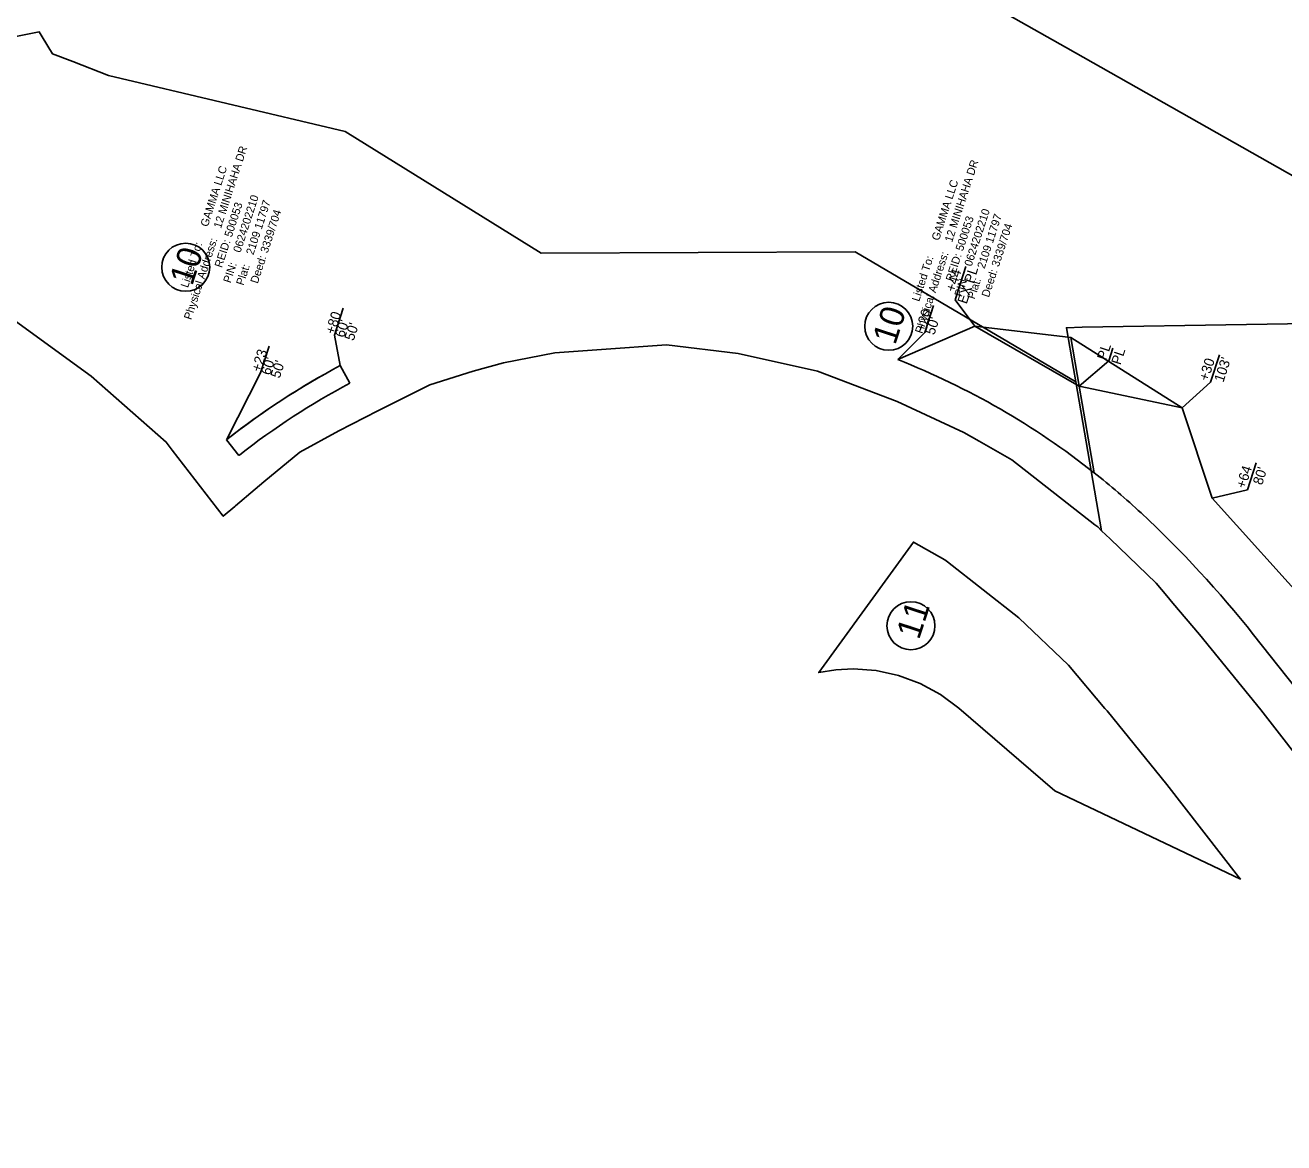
# Model space of a CAD drawing. Extents: x 1019969 to 1024963, y 638146 to 643978.
# Drawn here: x 1022170 to 1022798, y 639826 to 640385 of the extents above; entities that cross this region are included whole.
import ezdxf

# ---------------------------------------------------------------- set-up
doc = ezdxf.new("R2010")
doc.units = 0
for name, color, linetype in [('Old_Level_30', 7, 'Continuous'), ('Pattern 5', 7, 'Continuous'), ('Pattern 6', 7, 'Continuous'), ('Prop Easement Construction', 7, 'Continuous'), ('Prop Easement Construction Station Offsets', 7, 'Continuous'), ('Prop Parcel Number CELL', 7, 'Continuous'), ('Prop Parcel Owner Text', 7, 'Continuous'), ('Prop ROW RW Lines', 7, 'Continuous')]:
    doc.layers.add(name, color=color, linetype=linetype)

msp = doc.modelspace()

# ---------------------------------------------------------------- linework, layer by layer
at = {"layer": 'Old_Level_30'}
for points in [[(1022988.86, 640468.59), (1022949.84, 640356.28), (1022949.73, 640356.05), (1022940.94, 640338.75), (1022939.06, 640335.05), (1022948.94, 640320.64), (1022950.08, 640319.01), (1022927.01, 640297.25), (1022898.56, 640270.43), (1022898.48, 640270.34), (1022888.65, 640261.07), (1022888.56, 640260.99), (1022689.3, 640373.74), (1022582.7, 640434.06)], [(1022148.7, 640375.88), (1022176.6, 640381.39), (1022178.12, 640378.87), (1022183.21, 640370.43), (1022193.31, 640366.53), (1022211.12, 640359.66), (1022329.52, 640331.69), (1022427.3, 640270.8), (1022584.22, 640271.53), (1022694.52, 640206.46), (1022707.44, 640132.03), (1022705.45, 640133.95), (1022704.1, 640135), (1022662.55, 640167.57), (1022646.27, 640176.76), (1022638.51, 640181.14), (1022605.2, 640196.65), (1022565.48, 640211.83), (1022525.74, 640220.72), (1022490.07, 640225.03), (1022457.46, 640222.66), (1022434.16, 640220.91), (1022408.58, 640216.03), (1022393.41, 640211.79), (1022371.78, 640205), (1022345.75, 640191.98), (1022326.36, 640182.01), (1022306.78, 640171.26), (1022288.84, 640156.43), (1022284.55, 640152.82), (1022284.47, 640152.75), (1022274.59, 640144.45), (1022274.24, 640144.15), (1022268.5, 640139.32), (1022243.08, 640172.38), (1022240.04, 640176.35), (1022202.53, 640209.25), (1022162.87, 640238.08)], [(1022814.25, 640007.36), (1022786.96, 640042.51), (1022756.35, 640080.22), (1022743.08, 640095.93), (1022740.03, 640099.54), (1022734.65, 640105.92), (1022711.61, 640128.02), (1022707.44, 640132.03), (1022694.52, 640206.46), (1022693.36, 640213.1), (1022693.35, 640213.19), (1022689.81, 640233.51), (1022697.66, 640233.85), (1022861.98, 640236.45)]]:
    msp.add_lwpolyline(points, dxfattribs=at)
msp.add_lwpolyline([(1022690.83, 640064.81), (1022709.07, 640043.2), (1022710.12, 640041.95), (1022739.96, 640005.2), (1022775.74, 639959.13), (1022776.77, 639957.9), (1022684.01, 640002), (1022636.09, 640043.31), (1022626.86, 640050.19), (1022616.74, 640055.7), (1022605.94, 640059.71), (1022594.69, 640062.15), (1022583.2, 640062.97), (1022574.59, 640062.51), (1022566.08, 640061.14), (1022613.4, 640126.41), (1022629.11, 640117.55), (1022630.4, 640116.54), (1022666.07, 640088.57)], close=True, dxfattribs=at)
at = {"layer": 'Pattern 6'}
for p, q in [((1022644.09, 640234.25), (1022605.57, 640217.59)), ((1022696.24, 640204.35), (1022644.09, 640234.25)), ((1022747.67, 640193.56), (1022692.04, 640228.71)), ((1022692.04, 640228.71), (1022696.24, 640204.35)), ((1022331.77, 640205.78), (1022327.03, 640214.59)), ((1022605.57, 640217.59), (1022605.57, 640217.59)), ((1022703.71, 640161.05), (1022696.24, 640204.35)), ((1022696.24, 640204.35), (1022696.24, 640204.35)), ((1022696.24, 640204.35), (1022696.24, 640204.35)), ((1022696.24, 640204.35), (1022703.71, 640161.05)), ((1022762.71, 640148.33), (1022747.67, 640193.56)), ((1022270.14, 640177.44), (1022276.36, 640169.61)), ((1022965.65, 639922.52), (1022762.71, 640148.33)), ((1022783.3, 640080.08), (1022840.86, 640007.16))]:
    msp.add_line(p, q, dxfattribs=at)
msp.add_lwpolyline([(1022696.24, 640204.35), (1022644.09, 640234.25), (1022692.04, 640228.71)], close=True, dxfattribs=at)
for centre, radius, start, end in [((1022499.92, 639887.66), 369.83, 117.87073, 128.33147), ((1022462.98, 639856.64), 388.09, 51.66236, 68.44413), ((1022499.92, 639887.66), 359.83, 117.8594, 128.33147), ((1022499.92, 639887.66), 369.83, 128.33147, 128.41171), ((1022499.92, 639887.66), 359.83, 128.33147, 128.41171), ((1022462.98, 639856.64), 388.09, 47.09809, 51.66236), ((1022360.48, 639746.34), 538.67, 38.28466, 47.0981)]:
    msp.add_arc(centre, radius, start, end, dxfattribs=at)
at = {"layer": 'Prop Easement Construction'}
for p, q in [((1022605.57, 640217.59), (1022644.09, 640234.25)), ((1022696.24, 640204.35), (1022644.09, 640234.25)), ((1022331.77, 640205.78), (1022327.03, 640214.59)), ((1022747.67, 640193.56), (1022696.24, 640204.35)), ((1022762.71, 640148.33), (1022747.67, 640193.56)), ((1022276.36, 640169.61), (1022270.14, 640177.44)), ((1022967.3, 639920.68), (1022762.71, 640148.33))]:
    msp.add_line(p, q, dxfattribs=at)
msp.add_arc((1022499.92, 639887.66), 369.83, 117.87073, 128.41171, dxfattribs=at)
at = {"layer": 'Prop Easement Construction Station Offsets'}
for p, q in [((1022639.6, 640264.17), (1022634.17, 640247.47)), ((1022623.4, 640244.59), (1022619.02, 640231.12)), ((1022328.47, 640243.27), (1022324.09, 640229.8)), ((1022291.44, 640224.27), (1022287.13, 640211.01)), ((1022713.07, 640223.3), (1022711.04, 640217.04)), ((1022766.24, 640219.93), (1022761.83, 640206.37)), ((1022784.7, 640165.92), (1022780.32, 640152.46))]:
    msp.add_line(p, q, dxfattribs=at)
for points in [[(1022634.17, 640247.47), (1022644.09, 640234.25)], [(1022324.09, 640229.8), (1022327.03, 640214.59)], [(1022619.02, 640231.12), (1022605.57, 640217.59)], [(1022711.04, 640217.04), (1022696.24, 640204.35)], [(1022287.13, 640211.01), (1022270.14, 640177.44)], [(1022761.83, 640206.37), (1022747.67, 640193.56)], [(1022780.32, 640152.46), (1022762.71, 640148.33)]]:
    msp.add_lwpolyline(points, dxfattribs=at)
at = {"layer": 'Prop Parcel Number CELL'}
for p, q in [((1022249.77, 640263.77), (1022249.77, 640263.77)), ((1022601.05, 640234.23), (1022601.05, 640234.23)), ((1022612.16, 640084.58), (1022612.16, 640084.58))]:
    msp.add_line(p, q, dxfattribs=at)
for centre in [(1022249.77, 640263.77), (1022601.05, 640234.23), (1022612.16, 640084.58)]:
    msp.add_circle(centre, 12, dxfattribs=at)
at = {"layer": 'Prop ROW RW Lines'}
msp.add_arc((1022167.9, 640774.19), 948.09, 40.00236, 40.00236, dxfattribs=at)

# ---------------------------------------------------------------- texts
at = {"layer": 'Pattern 5'}
for s, p in [('12 MINIHAHA DR', (1022267.37, 640282.87)), ('GAMMA LLC', (1022260.8, 640283.68)), ('12 MINIHAHA DR', (1022632.7, 640275.96)), ('GAMMA LLC', (1022626.13, 640276.77)), ('500053', (1022272.77, 640278.47)), ('0624202210', (1022277.12, 640270.81)), ('2109 11797', (1022283.57, 640269.62)), ('3339/704', (1022290.7, 640270.54)), ('500053', (1022638.11, 640271.56)), ('0624202210', (1022642.45, 640263.9)), ('2109 11797', (1022648.9, 640262.72)), ('3339/704', (1022656.03, 640263.63)), ('Listed To:', (1022250.9, 640253.24)), ('Physical Address:', (1022252.53, 640237.22)), ('REID:', (1022267.83, 640263.25)), ('Physical Address:', (1022617.86, 640230.31)), ('REID:', (1022633.16, 640256.34)), ('PIN:', (1022272.17, 640255.59)), ('Plat:', (1022278.62, 640254.41)), ('Deed:', (1022285.75, 640255.32)), ('Listed To:', (1022616.24, 640246.34)), ('PIN:', (1022637.51, 640248.69)), ('Plat:', (1022643.96, 640247.5)), ('Deed:', (1022651.09, 640248.42))]:
    msp.add_text(s, height=4, rotation=71.9892, dxfattribs=at).set_placement(p)
at = {"layer": 'Prop Easement Construction Station Offsets'}
for s, p in [('+44', (1022634.01, 640251.02)), ('EX PL', (1022639.97, 640245.07)), ('+80', (1022324.06, 640229.81)), ('+20', (1022618.99, 640231.13)), ("50'", (1022623.8, 640229.57)), ("60'", (1022328.87, 640228.25)), ("50'", (1022333.67, 640226.68)), ('+23', (1022287.11, 640211.02)), ('PL', (1022709.7, 640216.96)), ('PL', (1022716.83, 640214.64)), ("60'", (1022291.91, 640209.46)), ("50'", (1022296.71, 640207.9)), ('+30', (1022760.56, 640206.52)), ("103'", (1022768.26, 640205.93)), ('+64', (1022779.12, 640152.8)), ("80'", (1022787.58, 640154.56))]:
    msp.add_text(s, height=5, rotation=71.99034, dxfattribs=at).set_placement(p)
at = {"layer": 'Prop Parcel Owner Text'}
for s, p in [('10', (1022253, 640254.06)), ('10', (1022604.28, 640224.52)), ('11', (1022616.15, 640077.19))]:
    msp.add_text(s, height=12.15, rotation=71.9892, dxfattribs=at).set_placement(p)

doc.saveas('drawing.dxf')
